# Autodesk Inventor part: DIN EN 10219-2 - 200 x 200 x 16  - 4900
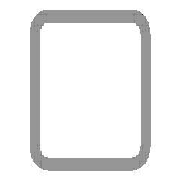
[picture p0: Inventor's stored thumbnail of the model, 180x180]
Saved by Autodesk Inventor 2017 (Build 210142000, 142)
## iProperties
IsCustomPart: 1
Created: 2017-11
Part Number: DIN EN 10219-2 - 200 x 200 x 16  - 4900
Material: Steel, Mild
Description: Cold formed welded structural hollow sections of non-alloy and fine grain structural steel
Document SubType Name: Modeling
Standard: DIN
Designer: iusti
Standard Revision: 2006-07
Standards Organization: DIN
Language: en-US
Size Designation: 200 x 200 x 16
Categories: <MemberInstance><Categories><Category DisplayName="Structural Shapes" InternalName="089c4875-fa83-4c05-b084-43b9cc11f5ed" Mnemonic="GRDR"><CategoryParameter Dis
Stock Number: 200 x 200 x 16
Density: 7.85 g/cm^3
Appearance: Semi-Polished
Mass: 410700 g
Surface Area: 65611.6 cm^2
Volume: 52318.5 cm^3
_CCFamilyMember: 103
_CCFamilyDisplayName: DIN EN 10219-2 (Square Hollow Section - Cold Formed) - Cold formed welded structural hollow sections of non-alloy and fine grain structural steel
_FrameMemberDoc: Frame Member File
_Version: 15.0.0
_GetPNFromCC: 1
G_L: 4900.000 mm
G_W: 200.000 mm
G_H: 200.000 mm
+9097C832-944A-4210-ACA6-A5D58FB62A7C+CUTDETAIL1: Cut
Author: iusti
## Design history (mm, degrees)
node "Start plane"
node "End plane"
sketch "Sketch"
  geometry: L1 (-100, -52)-(-100, 52); L2 (-52, 100)-(52, 100); L3 (100, 52)-(100, -52); L4 (52, -100)-(-52, -100); L5 (-52, 84)-(52, 84); L6 (84, 52)-(84, -52); L7 (52, -84)-(-52, -84); L8 (-84, -52)-(-84, 52); L9 (0, 293.918)-(0, -293.918) reference; L10 (-293.918, 0)-(293.918, 0) reference; A1 r 48 centre (-52, -52) between (-100, -52) and (-52, -100); A2 r 48 centre (-52, 52) between (-52, 100) and (-100, 52); A3 r 48 centre (52, 52) between (100, 52) and (52, 100); A4 r 48 centre (52, -52) between (52, -100) and (100, -52); A5 r 32 centre (-52, 52) between (-52, 84) and (-84, 52); A6 r 32 centre (52, 52) between (84, 52) and (52, 84); A7 r 32 centre (52, -52) between (52, -84) and (84, -52); A8 r 32 centre (-52, -52) between (-84, -52) and (-52, -84)
  constraints: 16 end point, 16 point on circle, 8 centre point, 8 tangent, 4 parallel, 3 equal radius, 2 perpendicular, 7 other
  dimensions: "d7" = 48 radius of A1 (= G_IR); "d10" = 200 distance between parallel lines of L2 L4 (= G_H); "d11" = 200 distance between parallel lines of L1 L3 (= G_W); "d12" = 16 distance between parallel lines of L3 L6 (= G_T); "d15" = 100 distance between parallel lines of L2 L10 (= 0.5 x d10); "d16" = 100 distance between parallel lines of L9 L3 (= 0.5 x d11)
extrude "Body" new body sketch "Sketch" stored distance "d3" = 4900 (= G_L); taper "d4" = 0 deg
node "Driven Length"
  sketch "Sketch3"
    geometry: L1 (0, 0)-(10, 0) reference
    constraints: 2 end point, 1 horizontal
  workplane "Work Plane3"
  sketch "Sketch4"
    geometry: L1 (-2, 100)-(12, 100) reference; L2 (-2, 5000)-(12, 5000) reference
    dimensions: "d18" = 4900 distance between parallel lines of L1 L2 (derived)
workplane "Work Plane4"
split "Split1"
body "Solid1"
other parameters: "G_W" = 200 [user parameter; used in 1 equation term], "G_H" = 200 [user parameter; used in 1 equation term], "G_T" = 16 [user parameter; used in 1 equation term], "G_IR" = 48 [user parameter; used in 1 equation term], "G_L" = 4900 (= d18) [user parameter; used in 1 equation term], "G_OFFSET_END" = 0 [user parameter; used in 1 equation term], "d17" = 90 deg
